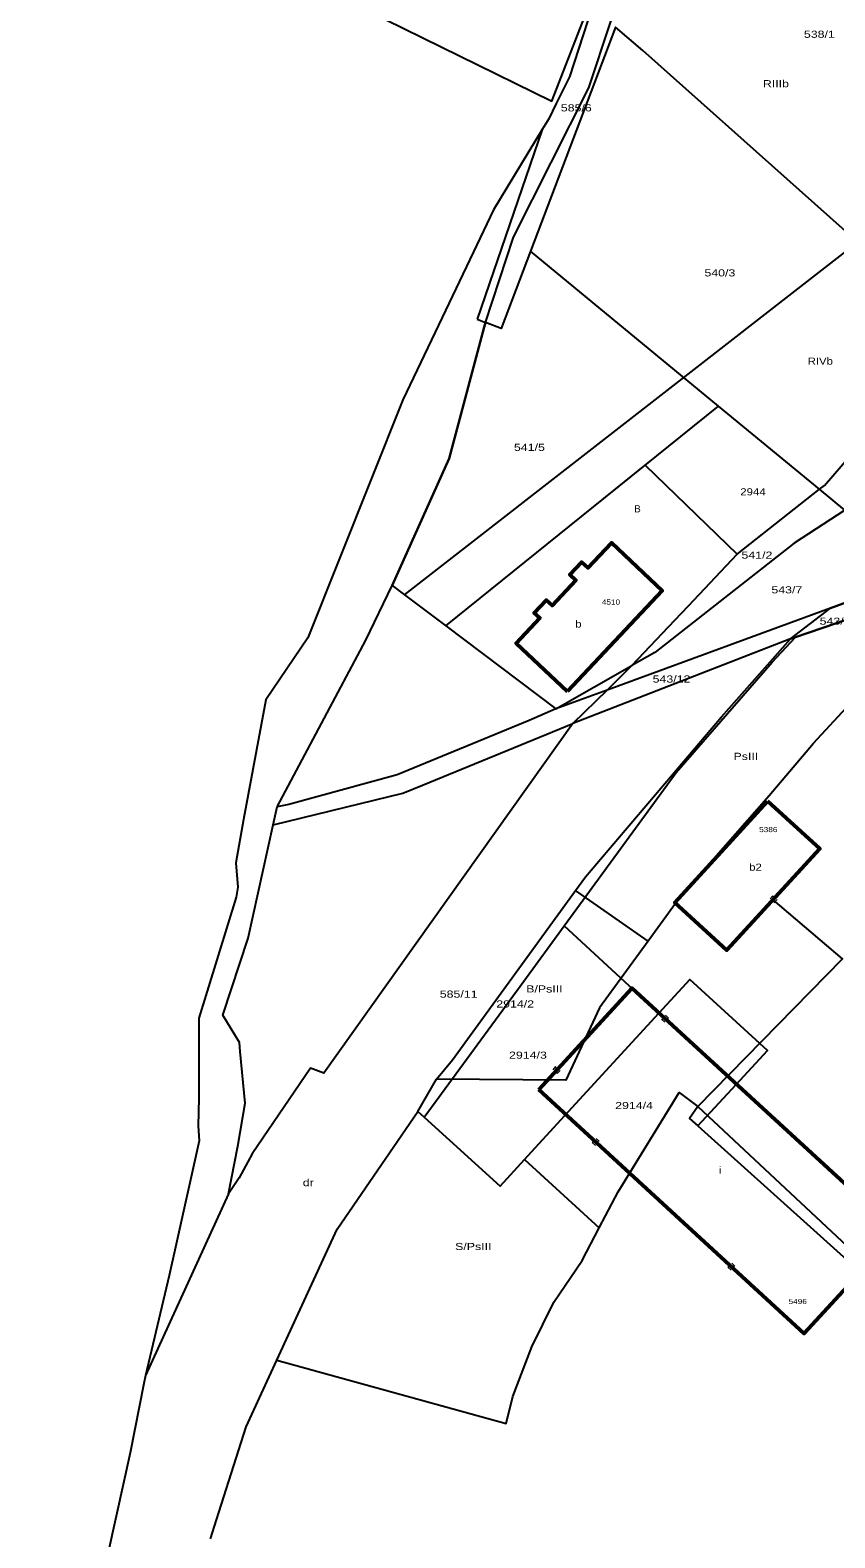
# Model space of a CAD drawing. Extents: x 4641351 to 4644672, y 5357112 to 5362385.
# Drawn here: x 4642821.1 to 4642962.5, y 5360710 to 5360975 of the extents above; entities that cross this region are included whole.
import ezdxf
from ezdxf.enums import TextEntityAlignment as Align

# ---------------------------------------------------------------- set-up
doc = ezdxf.new("R2010")
doc.units = 0
doc.header["$LTSCALE"] = 0.5
for name, color, linetype in [('24', 7, 'Continuous'), ('26', 7, 'Continuous'), ('4', 7, 'Continuous')]:
    doc.layers.add(name, color=color, linetype=linetype)
for name, color, linetype, lineweight in [('25', 7, 'Continuous', 25), ('27', 7, 'Continuous', 25), ('3', 7, 'Continuous', 13)]:
    doc.layers.add(name, color=color, linetype=linetype, lineweight=lineweight)

msp = doc.modelspace()

# ---------------------------------------------------------------- linework, layer by layer
at = {"layer": '25'}
msp.add_line((4642964.268, 5360890.656), (4642959.809, 5360894.332), dxfattribs=at)
for points in [[(4642821.057, 5361007.716), (4642864.076, 5360986.508), (4642912.752, 5360962.51), (4642918.613, 5360977.622), (4642923.104, 5360989.2), (4642926.231, 5360997.125), (4642928.342, 5361003.161), (4642868.277, 5361047.34), (4642876.521, 5361064.787), (4642849.439, 5361078.823), (4642842.673, 5361061.958), (4642834.971, 5361043.37), (4642821.583, 5361009.338)], [(4642884.704, 5360877.408), (4642886.846, 5360875.794), (4642894.1, 5360870.326), (4642917.967, 5360889.555), (4642942.05, 5360908.958), (4642908.982, 5360936.175), (4642903.817, 5360922.592), (4642901.098, 5360923.63), (4642900.836, 5360922.834), (4642894.697, 5360899.717)]]:
    msp.add_lwpolyline(points, close=True, dxfattribs=at)
for points in [[(4642899.612, 5360924.197), (4642901.098, 5360923.63), (4642906.024, 5360938.609), (4642919.248, 5360964.886), (4642923.046, 5360976.336), (4642929.733, 5360995.408), (4642940.745, 5361024.969), (4642950.415, 5361050.19), (4642946.748, 5361050.421), (4642933.62, 5361017.216)], [(4642923.104, 5360989.2), (4642915.822, 5360966.818), (4642913.523, 5360962.13), (4642912.212, 5360959.457), (4642911.048, 5360957.542), (4642899.612, 5360924.197)], [(4642959.809, 5360894.332), (4642960.663, 5360895.006), (4642984.379, 5360922.502), (4642977.547, 5360928.024), (4642966.547, 5360937.779), (4642928.717, 5360971.446), (4642923.955, 5360975.552), (4642908.982, 5360936.175)], [(4642961.719, 5360873.449), (4642966.205, 5360875.094), (4642971.614, 5360881.095), (4643003.059, 5360915.975), (4642999.77, 5360918.699), (4642994.247, 5360913.207), (4642984.526, 5360904.064), (4642964.268, 5360890.656), (4642955.311, 5360884.878), (4642930.858, 5360865.649), (4642926.797, 5360863.336), (4642922.443, 5360859.045)], [(4642894.1, 5360870.326), (4642913.439, 5360855.743), (4642926.797, 5360863.336), (4642934.336, 5360871.3), (4642936.776, 5360873.868), (4642945.323, 5360882.902), (4642959.809, 5360894.332), (4642942.05, 5360908.958)], [(4642938.39, 5360782.43), (4642958.734, 5360764.143), (4642975.77, 5360748.826), (4642979.077, 5360746.004), (4642979.936, 5360747.03), (4642980.927, 5360748.211), (4643012.937, 5360786.377), (4643014.684, 5360788.461), (4643026.742, 5360802.84), (4643036.653, 5360814.656), (4643043.329, 5360822.616), (4643030.257, 5360835.336), (4642988.127, 5360876.348), (4642985.672, 5360878.737), (4642962.597, 5360870.762), (4642955.59, 5360868.34)], [(4642954.708, 5360868.034), (4642961.719, 5360873.449), (4642922.443, 5360859.045), (4642916.454, 5360853.141)], [(4642852.751, 5360709.853), (4642853.815, 5360713.188), (4642859.042, 5360729.574), (4642864.42, 5360741.249), (4642875.028, 5360764.278), (4642889.172, 5360784.982), (4642892.458, 5360790.663), (4642895.282, 5360794.037), (4642916.924, 5360823.783), (4642918.692, 5360826.213), (4642942.552, 5360854.355), (4642954.708, 5360868.034), (4642916.454, 5360853.141), (4642872.691, 5360791.714), (4642870.335, 5360792.567), (4642860.094, 5360777.524), (4642857.779, 5360773.32), (4642855.939, 5360770.516), (4642841.346, 5360738.559), (4642841.065, 5360737.144), (4642838.64, 5360724.95), (4642833.603, 5360702.196)], [(4642889.172, 5360784.982), (4642890.31, 5360783.95), (4642907.81, 5360807.9), (4642914.89, 5360817.59), (4642934.59, 5360844.55), (4642951.46, 5360863.91), (4642955.59, 5360868.34), (4642954.708, 5360868.034)], [(4642890.31, 5360783.95), (4642903.65, 5360771.87), (4642907.95, 5360776.55), (4642915, 5360784.21), (4642931.58, 5360802.23), (4642927.17, 5360806.29), (4642914.89, 5360817.59)], [(4642907.95, 5360776.55), (4642921.09, 5360764.54), (4642924.397, 5360770.846), (4642935.125, 5360788.291), (4642938.4, 5360785.837), (4642936.962, 5360783.718), (4642938.39, 5360782.43), (4642945.14, 5360789.74), (4642950.63, 5360795.69), (4642937.02, 5360808.15), (4642931.58, 5360802.23)]]:
    msp.add_lwpolyline(points, dxfattribs=at)
at = {"layer": '27'}
for p, q in [((4642926.797, 5360863.336), (4642922.443, 5360859.045)), ((4642929.655, 5360814.892), (4642916.924, 5360823.783))]:
    msp.add_line(p, q, dxfattribs=at)
for points in [[(4642884.704, 5360877.408), (4642886.846, 5360875.794), (4642966.547, 5360937.779), (4642999.567, 5360973.297), (4642990.074, 5360981.168), (4642942.243, 5361023.638), (4642940.745, 5361024.969)], [(4642886.846, 5360875.794), (4642894.1, 5360870.326), (4642917.967, 5360889.555), (4642929.131, 5360898.549), (4642945.323, 5360882.902), (4642959.809, 5360894.332), (4642960.663, 5360895.006), (4642984.379, 5360922.502), (4643015.77, 5360958.066), (4643023.019, 5360966.278), (4643038.251, 5360978.818), (4643044.739, 5360984.135), (4643025.403, 5360999.23), (4643020.004, 5360993.811), (4642999.567, 5360973.297)], [(4642923.104, 5360989.2), (4642915.822, 5360966.818), (4642913.523, 5360962.13), (4642912.212, 5360959.457), (4642911.048, 5360957.542), (4642902.489, 5360943.459), (4642899.559, 5360937.297), (4642893.486, 5360924.523), (4642886.572, 5360910.023), (4642869.835, 5360868.223), (4642862.471, 5360857.347), (4642858.542, 5360836.297), (4642857.208, 5360828.665), (4642857.557, 5360824.392), (4642857.253, 5360822.649), (4642850.689, 5360801.349), (4642850.695, 5360799.023), (4642850.727, 5360787.333), (4642850.583, 5360782.461), (4642850.747, 5360779.836), (4642846.595, 5360761.114), (4642845.492, 5360756.143), (4642841.346, 5360738.559)], [(4642855.939, 5360770.516), (4642857.53, 5360778.854), (4642858.844, 5360786.454), (4642857.995, 5360795.529), (4642857.85, 5360797.079), (4642854.932, 5360801.877), (4642859.392, 5360815.442), (4642863.778, 5360835.323), (4642864.482, 5360838.514), (4642880.035, 5360867.819), (4642884.704, 5360877.408), (4642894.697, 5360899.717), (4642900.836, 5360922.834), (4642901.098, 5360923.63), (4642906.024, 5360938.609), (4642919.248, 5360964.886), (4642923.046, 5360976.336)], [(4642954.708, 5360868.034), (4642955.59, 5360868.34), (4642962.597, 5360870.762), (4642985.672, 5360878.737), (4642986.592, 5360880.024), (4642990.368, 5360883.956), (4642966.205, 5360875.094), (4642961.719, 5360873.449), (4642922.443, 5360859.045), (4642913.439, 5360855.743), (4642908.738, 5360853.709), (4642885.535, 5360844.16), (4642866.506, 5360838.934), (4642864.482, 5360838.514)], [(4642894.1, 5360870.326), (4642913.439, 5360855.743), (4642926.797, 5360863.336), (4642934.336, 5360871.3), (4642936.776, 5360873.868), (4642945.323, 5360882.902)], [(4642934.508, 5360821.537), (4642935.707, 5360823.178), (4642950.956, 5360840.529), (4642958.74, 5360849.687), (4642963.785, 5360855.129), (4642969.95, 5360861.779), (4642985.672, 5360878.737)], [(4642852.751, 5360709.853), (4642853.815, 5360713.188), (4642859.042, 5360729.574), (4642864.42, 5360741.249), (4642875.028, 5360764.278), (4642889.172, 5360784.982), (4642892.458, 5360790.663), (4642895.282, 5360794.037), (4642916.924, 5360823.783), (4642918.692, 5360826.213), (4642942.552, 5360854.355), (4642954.708, 5360868.034), (4642916.454, 5360853.141), (4642872.691, 5360791.714), (4642870.335, 5360792.567), (4642860.094, 5360777.524), (4642857.779, 5360773.32), (4642855.939, 5360770.516), (4642841.346, 5360738.559), (4642841.065, 5360737.144), (4642838.64, 5360724.95), (4642833.603, 5360702.196)], [(4642863.778, 5360835.323), (4642886.563, 5360840.905), (4642890.04, 5360842.328), (4642916.454, 5360853.141)], [(4642864.42, 5360741.249), (4642904.695, 5360730.14), (4642905.897, 5360734.858), (4642909.222, 5360743.582), (4642913.126, 5360751.433), (4642918.085, 5360758.796), (4642921.09, 5360764.54), (4642924.397, 5360770.846), (4642935.125, 5360788.291), (4642938.4, 5360785.837), (4642963.816, 5360811.825), (4642951.631, 5360822.167), (4642943.532, 5360813.297), (4642934.508, 5360821.537), (4642929.655, 5360814.892), (4642921.095, 5360803.173), (4642915.206, 5360790.475), (4642892.458, 5360790.663)], [(4642938.4, 5360785.837), (4642979.936, 5360747.03), (4642980.927, 5360748.211), (4643012.937, 5360786.377), (4642965.756, 5360813.808)]]:
    msp.add_lwpolyline(points, dxfattribs=at)
at = {"layer": '3'}
for p, q in [((4642951.617, 5360822.892), (4642951.111, 5360822.338)), ((4642951.617, 5360822.892), (4642951.849, 5360821.664)), ((4642952.355, 5360822.218), (4642951.849, 5360821.664)), ((4642932.043, 5360801.169), (4642933.271, 5360801.397)), ((4642932.043, 5360801.169), (4642932.595, 5360800.661)), ((4642932.719, 5360801.905), (4642933.271, 5360801.397)), ((4642912.959, 5360792.308), (4642913.467, 5360792.86)), ((4642913.695, 5360791.632), (4642913.467, 5360792.86)), ((4642913.695, 5360791.632), (4642914.203, 5360792.184)), ((4642921.069, 5360779.732), (4642919.841, 5360779.504)), ((4642920.393, 5360778.996), (4642919.841, 5360779.504)), ((4642921.069, 5360779.732), (4642920.517, 5360780.24)), ((4642944.922, 5360757.807), (4642943.694, 5360757.579)), ((4642944.246, 5360757.071), (4642943.694, 5360757.579)), ((4642944.922, 5360757.807), (4642944.37, 5360758.315))]:
    msp.add_line(p, q, dxfattribs=at)
at = {"layer": '3', "lineweight": 53}
for points in [[(4642915.51, 5360858.77), (4642906.464, 5360867.276), (4642910.628, 5360871.704), (4642909.665, 5360872.61), (4642911.775, 5360874.854), (4642912.783, 5360873.907), (4642916.961, 5360878.352), (4642915.924, 5360879.327), (4642917.984, 5360881.52), (4642919.077, 5360880.493), (4642923.215, 5360884.899), (4642932.16, 5360876.497)], [(4642950.65, 5360839.538), (4642959.835, 5360831.151), (4642943.532, 5360813.297), (4642934.347, 5360821.684)], [(4642910.437, 5360788.826), (4642926.819, 5360806.649), (4642973.492, 5360763.749), (4642957.11, 5360745.926)]]:
    msp.add_lwpolyline(points, close=True, dxfattribs=at)

# ---------------------------------------------------------------- texts
at = {"layer": '24'}
for s, width, p in [('538/1', 1.3, (4642957.046, 5360973.669)), ('585/6', 1.3, (4642914.324, 5360960.734)), ('540/3', 1.3, (4642939.561, 5360931.733)), ('541/5', 1.3, (4642906.084, 5360901.068)), ('2944', 1.2, (4642945.864, 5360893.255)), ('541/2', 1.3, (4642946.075, 5360882.129)), ('543/7', 1.3, (4642951.328, 5360876.03)), ('543/13', 1.3, (4642959.811, 5360870.519)), ('543/12', 1.3, (4642930.46, 5360860.354)), ('585/11', 1.3, (4642893.045, 5360804.975)), ('2914/2', 1.3, (4642902.979, 5360803.243)), ('2914/3', 1.3, (4642905.222, 5360794.244)), ('2914/4', 1.3, (4642923.877, 5360785.396))]:
    msp.add_text(s, height=1.25, dxfattribs=dict(at, width=width)).set_placement(p)
at = {"layer": '26'}
for s, width, p in [('RIIIb', 1.3, (4642949.84, 5360964.983)), ('RIVb', 1.2, (4642957.698, 5360916.234)), ('PsIII', 1.3, (4642944.682, 5360846.764)), ('B/PsIII', 1.3, (4642908.244, 5360805.883)), ('dr', 1.3, (4642868.973, 5360771.843)), ('S/PsIII', 1.3, (4642895.74, 5360760.618))]:
    msp.add_text(s, height=1.25, dxfattribs=dict(at, width=width)).set_placement(p)
msp.add_text('B', height=1.25, dxfattribs=at).set_placement((4642927.254, 5360890.277))
at = {"layer": '4', "width": 1.2}
for s, p in [('4510', (4642921.536, 5360874.057)), ('5386', (4642949.178, 5360834.066)), ('5496', (4642954.359, 5360751.125))]:
    msp.add_text(s, height=0.9, dxfattribs=at).set_placement(p)
at = {"layer": '4'}
for s, width, p in [('b', 1.2, (4642917.405, 5360870.024)), ('b2', 1.2, (4642948.54, 5360827.279)), ('i', 1.3, (4642942.344, 5360774.034))]:
    msp.add_text(s, height=1.25, dxfattribs=dict(at, width=width)).set_placement(p, align=Align.CENTER)

doc.saveas('drawing.dxf')
